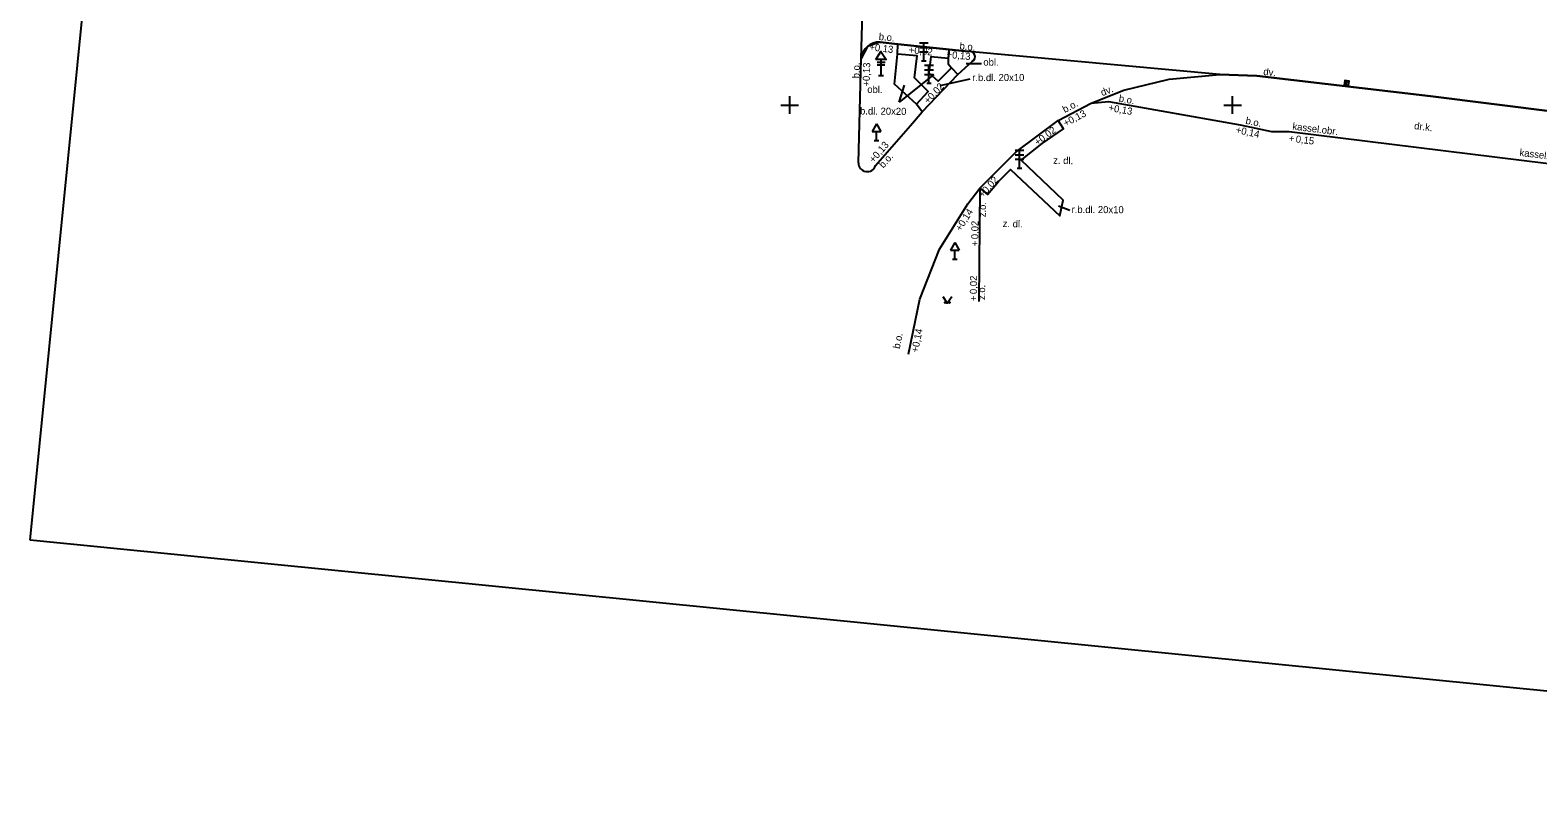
# Model space of a CAD drawing. Extents: x -598693 to -598360, y -1162453 to -1162007.
# Drawn here: x -598692.9 to -598607.8, y -1162439.3 to -1162395.8 of the extents above; entities that cross this region are included whole.
import ezdxf

# ---------------------------------------------------------------- set-up
doc = ezdxf.new("R2010")
doc.units = 0
for name, color, linetype in [('Vrstva 14', 7, 'Continuous'), ('Vrstva 19', 7, 'Continuous'), ('Vrstva 2', 7, 'Continuous'), ('Vrstva 25', 7, 'Continuous'), ('Vrstva 44', 7, 'Continuous'), ('Vrstva 49', 7, 'Continuous'), ('Vrstva 50', 7, 'Continuous'), ('Vrstva 62', 7, 'Continuous'), ('Vrstva 63', 7, 'Continuous'), ('Vrstva 7', 7, 'Continuous')]:
    doc.layers.add(name, color=color, linetype=linetype)

msp = doc.modelspace()

# ---------------------------------------------------------------- linework, layer by layer
at = {"layer": 'Vrstva 14'}
msp.add_lwpolyline([(-598641.354, -1162410.802), (-598641.104, -1162411.177), (-598640.854, -1162410.802)], dxfattribs=at)
for centre in [(-598641.229, -1162411.152), (-598640.979, -1162411.152)]:
    msp.add_circle(centre, 0.025, dxfattribs=at)
at = {"layer": 'Vrstva 19'}
for p, q in [((-598642.18, -1162396.5), (-598642.68, -1162396.5)), ((-598642.68, -1162396.75), (-598642.18, -1162396.75)), ((-598642.68, -1162397), (-598642.18, -1162397)), ((-598642.43, -1162397.5), (-598642.43, -1162396.5)), ((-598642.555, -1162397.5), (-598642.305, -1162397.5)), ((-598641.89, -1162397.77), (-598642.39, -1162397.77)), ((-598642.39, -1162398.02), (-598641.89, -1162398.02)), ((-598642.14, -1162398.77), (-598642.14, -1162397.77)), ((-598642.39, -1162398.27), (-598641.89, -1162398.27)), ((-598642.265, -1162398.77), (-598642.015, -1162398.77)), ((-598645.1, -1162401.067), (-598645.35, -1162401.5)), ((-598645.1, -1162401.067), (-598644.85, -1162401.5)), ((-598645.35, -1162401.5), (-598644.85, -1162401.5)), ((-598645.225, -1162402), (-598644.975, -1162402)), ((-598645.1, -1162402), (-598645.1, -1162401.5)), ((-598636.78, -1162402.56), (-598637.28, -1162402.56)), ((-598637.28, -1162402.81), (-598636.78, -1162402.81)), ((-598637.28, -1162403.06), (-598636.78, -1162403.06)), ((-598637.03, -1162403.56), (-598637.03, -1162402.56)), ((-598637.155, -1162403.56), (-598636.905, -1162403.56)), ((-598640.68, -1162407.767), (-598640.93, -1162408.2)), ((-598640.93, -1162408.2), (-598640.43, -1162408.2)), ((-598640.68, -1162407.767), (-598640.43, -1162408.2)), ((-598640.68, -1162408.7), (-598640.68, -1162408.2)), ((-598640.805, -1162408.7), (-598640.555, -1162408.7))]:
    msp.add_line(p, q, dxfattribs=at)
at = {"layer": 'Vrstva 2'}
msp.add_lwpolyline([(-598692.873, -1162424.561), (-598651.24, -1162006.63), (-598503.471, -1162021.35), (-598545.104, -1162439.282)], close=True, dxfattribs=at)
msp.add_lwpolyline([(-598692.873, -1162424.561), (-598651.24, -1162006.63), (-598503.471, -1162021.35), (-598545.104, -1162439.282)], close=True, dxfattribs=at)
at = {"layer": 'Vrstva 25'}
msp.add_line((-598618.574, -1162398.884), (-598618.546, -1162398.636), dxfattribs=at)
msp.add_lwpolyline([(-598618.449, -1162398.898), (-598618.422, -1162398.649), (-598618.671, -1162398.622), (-598618.698, -1162398.871)], close=True, dxfattribs=at)
at = {"layer": 'Vrstva 44'}
for p, q in [((-598645.066, -1162397.582), (-598644.618, -1162397.582)), ((-598645.066, -1162397.732), (-598644.623, -1162397.732)), ((-598644.846, -1162397.432), (-598644.846, -1162398.332)), ((-598644.996, -1162398.332), (-598644.696, -1162398.332))]:
    msp.add_line(p, q, dxfattribs=at)
msp.add_lwpolyline([(-598645.146, -1162397.437), (-598644.846, -1162396.982), (-598644.546, -1162397.437)], close=True, dxfattribs=at)
at = {"layer": 'Vrstva 49'}
for p, q in [((-598640.04, -1162397.66), (-598639.18, -1162397.66)), ((-598641.86, -1162398.27), (-598643.816, -1162399.841)), ((-598643.816, -1162399.841), (-598643.51, -1162398.88)), ((-598641.5, -1162398.89), (-598639.81, -1162398.53)), ((-598634.83, -1162405.69), (-598634.19, -1162405.94))]:
    msp.add_line(p, q, dxfattribs=at)
at = {"layer": 'Vrstva 62'}
for p, q in [((-598650, -1162400.5), (-598650, -1162399.5)), ((-598625, -1162400.5), (-598625, -1162399.5)), ((-598650.5, -1162400), (-598649.5, -1162400)), ((-598625.5, -1162400), (-598624.5, -1162400))]:
    msp.add_line(p, q, dxfattribs=at)
at = {"layer": 'Vrstva 63'}
msp.add_lwpolyline([(-598530.28, -1162409.94), (-598547.75, -1162407.77), (-598558.64, -1162406.42), (-598581.59, -1162403.59), (-598599.75, -1162401.27), (-598613.83, -1162399.49), (-598623.63, -1162398.36), (-598625.72, -1162398.27), (-598639.91, -1162396.97), (-598643.9, -1162396.57), (-598644.89, -1162396.45), (-598645.61, -1162396.69), (-598645.96, -1162397.37), (-598645.75, -1162390.37), (-598645.62, -1162385.09), (-598645.7, -1162378.05), (-598641.8, -1162378.3), (-598642.13, -1162376.31), (-598642.05, -1162373.23), (-598641.85, -1162368.87), (-598640.89, -1162354.82), (-598639.77, -1162342.39), (-598638.09, -1162327.94)], dxfattribs=at)
at = {"layer": 'Vrstva 7'}
for points in [[(-598644.89, -1162396.45), (-598643.9, -1162396.57), (-598641.01, -1162396.86), (-598639.91, -1162396.97)], [(-598642.52, -1162400.39), (-598642.85, -1162399.96), (-598644.09, -1162398.82), (-598643.92, -1162397.12), (-598643.9, -1162396.57)], [(-598642.85, -1162399.96), (-598642.18, -1162399.24), (-598642.96, -1162398.46), (-598642.8, -1162397.22), (-598643.92, -1162397.12)], [(-598641.01, -1162396.86), (-598641.06, -1162397.38), (-598641.06, -1162397.67), (-598640.87, -1162397.9), (-598640.51, -1162398.27)], [(-598646.12, -1162403.26), (-598645.96, -1162397.37)], [(-598645.15, -1162403.42), (-598643.18, -1162401.15), (-598642.52, -1162400.39), (-598640.51, -1162398.27), (-598639.69, -1162397.53)], [(-598641.06, -1162397.38), (-598642.03, -1162397.28), (-598642.14, -1162398.18), (-598641.61, -1162398.66), (-598640.87, -1162397.9)], [(-598632.99, -1162399.9), (-598631.14, -1162399.17), (-598628.58, -1162398.54), (-598625.72, -1162398.27), (-598623.63, -1162398.36), (-598613.83, -1162399.49), (-598599.75, -1162401.27), (-598598.66, -1162402.55), (-598598.76, -1162402.66)], [(-598643.29, -1162414.06), (-598642.66, -1162410.96), (-598641.55, -1162408.14), (-598639.95, -1162405.58), (-598639.26, -1162404.7), (-598637.21, -1162402.65), (-598634.85, -1162400.87), (-598632.99, -1162399.9), (-598632.01, -1162399.8), (-598624.57, -1162401.12), (-598622.81, -1162401.5)], [(-598639.26, -1162404.7), (-598638.84, -1162405.05), (-598638.22, -1162404.32), (-598637.53, -1162403.64), (-598634.75, -1162406.26), (-598634.56, -1162405.37), (-598636.93, -1162403.12), (-598635.74, -1162402.17), (-598634.54, -1162401.35), (-598634.85, -1162400.87)], [(-598622.81, -1162401.5), (-598621.8, -1162401.5), (-598605.79, -1162403.47), (-598604.81, -1162403.68)], [(-598639.26, -1162404.7), (-598639.33, -1162411.1)]]:
    msp.add_lwpolyline(points, dxfattribs=at)
for centre, radius, start, end in [((-598644.954, -1162397.458), 1.01, 86.35947, 175.01928), ((-598639.842, -1162397.266), 0.304, 299.90276, 102.99271), ((-598645.622, -1162403.263), 0.498, 179.70844, 341.55854)]:
    msp.add_arc(centre, radius, start, end, dxfattribs=at)

# ---------------------------------------------------------------- texts
at = {"layer": 'Vrstva 49'}
for s, rotation, p in [('b.o.', 354.28941, (-598644.986, -1162396.32)), ('b.o.', 354.28941, (-598640.426, -1162396.85)), ('b.o.', 88.44396, (-598646.06, -1162398.497)), ('obl.', 359.79064, (-598639.069, -1162397.774)), ('dv.', 353.42249, (-598623.281, -1162398.299)), ('obl.', 359.64523, (-598645.621, -1162399.317)), ('r.b.dl. 20x10', 0.09226, (-598639.697, -1162398.649)), ('dv.', 21.53392, (-598632.353, -1162399.502)), ('b.o.', 349.93931, (-598631.446, -1162399.804)), ('b.dl. 20x20', 359.3654, (-598646.031, -1162400.531)), ('b.o.', 27.54228, (-598634.472, -1162400.455)), ('b.o.', 347.81634, (-598624.294, -1162401.056)), ('kassel.obr.', 352.98513, (-598621.638, -1162401.386)), ('dr.k.', 352.98513, (-598614.768, -1162401.358)), ('b.o.', 49.0472, (-598644.711, -1162403.592)), ('z. dl.', 358.69517, (-598635.131, -1162403.317)), ('kassel.obr.', 352.98513, (-598608.82, -1162402.866)), ('z.o.', 89.37335, (-598638.93, -1162406.339)), ('r.b.dl. 20x10', 359.64827, (-598634.091, -1162406.092)), ('z. dl.', 358.69517, (-598637.981, -1162406.886)), ('z.o.', 89.37335, (-598638.973, -1162411.009)), ('b.o.', 78.51246, (-598643.79, -1162413.784))]:
    msp.add_text(s, height=0.4, rotation=rotation, dxfattribs=at).set_placement(p)
at = {"layer": 'Vrstva 50'}
for s, rotation, p in [('+0,13', 353.08877, (-598645.521, -1162396.906)), ('+0,02', 354.26978, (-598643.293, -1162397.072)), ('+0,13', 354.28941, (-598641.158, -1162397.33)), ('+0,13', 88.44396, (-598645.488, -1162398.962)), ('+0,02', 46.52568, (-598642.184, -1162399.963)), ('+0,13', 27.54228, (-598634.423, -1162401.23)), ('+0,13', 349.93931, (-598632.028, -1162400.328)), ('+0,02', 37.02496, (-598636.003, -1162402.313)), ('+0,14', 347.81634, (-598624.849, -1162401.574)), ('+0,13', 49.0472, (-598645.258, -1162403.292)), ('+', 352.98513, (-598621.843, -1162402.061)), ('0,15', 352.98513, (-598621.453, -1162402.109)), ('+0,02', 48.4667, (-598639.09, -1162405.255)), ('+0,14', 57.99462, (-598640.342, -1162407.16)), ('0,02', 89.37335, (-598639.351, -1162407.575)), ('+', 89.37335, (-598639.355, -1162407.969)), ('0,02', 89.37335, (-598639.433, -1162410.675)), ('+', 89.37335, (-598639.438, -1162411.068)), ('+0,14', 78.51246, (-598642.76, -1162413.998))]:
    msp.add_text(s, height=0.4, rotation=rotation, dxfattribs=at).set_placement(p)

doc.saveas('drawing.dxf')
